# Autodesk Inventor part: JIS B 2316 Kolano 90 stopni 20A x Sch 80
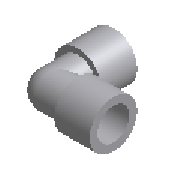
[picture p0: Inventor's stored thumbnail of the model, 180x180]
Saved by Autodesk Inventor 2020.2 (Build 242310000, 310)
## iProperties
Manager: www.cadconsulting.pl
Company: Fabian Stasiak CAD Consulting
Created: 2014-02
Part Number: JIS B 2316 Kolano 90 stopni 20A x Sch 80
Material: Stal
Description: Kolano
Document SubType Name: Modeling
Standard: JIS B 2316
Designer: F.Stasiak
Standards Organization: JIS
Language: pl-PL
Size Designation: 20A x Sch 80
Categories: <MemberInstance><Categories><Category DisplayName="Rury cienko- i grubościenne" InternalName="4347fa0f-2144-441d-94cd-e3e15c92b736" Mnemonic="TUBEANDPIPE"><Cate
Density: 1 g/cm^3
Appearance: Płyta
Catalog Web Link: www.expertbooks.pl
NAME: PIPING: JIS B 2316 90 Deg Elbow
DATA: <meta><inlinegroups number="0" deflen="0"></inlinegroups><connections number="2"></connections><angles><a>1.5707963267949</a></angles></meta>
IsCustomPart: 0
Author: F.Stasiak
Subject: Zbiór ćwiczeń. Autodesk Inventor 2020. Kurs Professional
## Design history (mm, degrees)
sketch "Sketch1"
  geometry: L1 (0, 0)-(0, 31.8); L2 (0, 31.8)-(-31.8, 31.8); L3 (0, 0)-(-31.8, 0); L4 (-31.8, 0)-(-31.8, 31.8); L5 (0, 31.8)-(-31.8, 0)
  constraints: 10 end point, 2 parallel, 1 coincident, 1 perpendicular, 1 vertical
  dimensions: "d8" = 31.8 distance of L1.start L1.end (= G + C1); "d9" = 31.8 distance of L1.end L2.end (= G + C1)
workplane "Work Plane1"
sketch "Sketch2"
  geometry: C1 r 10.7 at (0, 0); C2 r 15 at (0, 0)
  constraints: 2 centre point, 1 coincident, 1 concentric
  dimensions: "d0" = 21.4 diameter of C1 (= D); "d1" = 30 diameter of C2 (= D + 2 x T)
extrude "Extrusion1" new body sketch "Sketch2" taper "d2" = 0 deg; stored distance "d49" = 46.8 (= C1 + G + T + 0.5 x D)
workplane "Work Plane2"
sketch "Sketch3"
  geometry: L1 (0, 31.8)-(0, 0); L2 (-15, 0)-(15, 0) reference; C1 r 15 at (0, 31.8); C2 r 10.7 at (0, 31.8)
  constraints: 2 centre point, 2 end point, 1 coincident, 1 concentric, 1 midpoint, 1 vertical
  dimensions: "d4" = 31.8 distance of L1.start L1.end (= G + C1); "d5" = 21.4 diameter of C2 (= D); "d6" = 30 diameter of C1 (= D + 2 x T)
extrude "Extrusion2" join sketch "Sketch3" taper "d7" = 0 deg; stored distance "d55" = 46.8 (= C1 + G + 0.5 x D + T)
sketch "Sketch4"
  geometry: C1 r 15 at (0, 0) reference; C2 r 17.9 at (0, 0)
  constraints: 1 centre point, 1 coincident, 1 concentric
  dimensions: "d11" = 35.8 diameter of C2 (= S + 2 x T)
extrude "Extrusion3" join sketch "Sketch4" distance "d12" = 17 (= C1 + T); taper "d13" = 0 deg
sketch "Sketch5"
  geometry: C1 r 15 at (0, 0) reference; C2 r 17.9 at (0, 0)
  constraints: 1 centre point, 1 coincident, 1 concentric
  dimensions: "d14" = 35.8 diameter of C2 (= S + 2 x T)
extrude "Extrusion4" join sketch "Sketch5" distance "d15" = 17 (= C1 + T); taper "d16" = 0 deg
sketch "Sketch6"
  geometry: C1 r 10.7 at (0, 0) reference; C2 r 13.6 at (0, 0)
  constraints: 1 centre point, 1 coincident, 1 concentric
  dimensions: "d17" = 27.2 diameter of C2 (= S)
extrude "Extrusion5" cut sketch "Sketch6" distance "d18" = 12.7 (= C1); taper "d19" = 0 deg
sketch "Sketch7"
  geometry: C1 r 10.7 at (0, 0) reference; C2 r 13.6 at (0, 0)
  constraints: 1 centre point, 1 coincident, 1 concentric
  dimensions: "d20" = 27.2 diameter of C2 (= S)
extrude "Extrusion6" cut sketch "Sketch7" distance "d21" = 12.7 (= C1); taper "d22" = 0 deg
fillet "Fillet1" dims "d23" = 6.2 (= G - 3 x T), "d24" = 10.5 (= G - 2 x T)
workaxis "Work Axis1"
workpoint "Work Point1"
workpoint "Work Point2"
workaxis "Work Axis2"
workpoint "Work Point3"
workpoint "Work Point4"
body "Solid1"
other parameters: "S" = 27.2 [user parameter; used in 4 equation terms], "D" = 21.4 [user parameter; used in 6 equation terms], "T" = 4.3 [user parameter; used in 10 equation terms], "C1" = 12.7 [user parameter; used in 10 equation terms], "G" = 19.1 [user parameter; used in 8 equation terms], "d3" = 31.8 (= G + C1), "d10" = 90 deg, "Size_Designation" = 12.345 [user parameter]
